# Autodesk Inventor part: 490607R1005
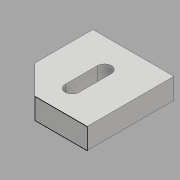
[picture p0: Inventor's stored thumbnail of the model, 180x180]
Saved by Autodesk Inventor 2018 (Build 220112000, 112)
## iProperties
Created: 2019-06
Part Number: 490607R1005
Material: 일반
Document SubType Name: Modeling
Designer: 6507_11
Density: 1 g/cm^3
Appearance: 기본값
Author: 6507_11
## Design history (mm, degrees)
sketch "스케치1"
  geometry: L1 (35, 37.5)-(-35, 37.5); L2 (-35, 37.5)-(-35, -12.5); L3 (-10, -37.5)-(35, -37.5); L4 (35, -37.5)-(35, 37.5); L5 (35, 37.5)-(-35, -37.5); L6 (-35, 37.5)-(35, -37.5); L7 (-10, -37.5)-(-35, -12.5); L8 (-35, 37.5)-(-35, -15.5); L9 (-35, -15.5)-(0, -15.5); L10 (6, 12.5)-(6, -15.5); L11 (-6, 12.5)-(-6, -15.5); A1 r 6 centre (0, -15.5) between (-6, -15.5) and (6, -15.5); A2 r 6 centre (0, 12.5) between (6, 12.5) and (-6, 12.5); 1 further point
  constraints: 22 end point, 4 point on circle, 3 parallel, 2 centre point, 2 midpoint, 2 perpendicular, 2 tangent, 1 coincident, 1 horizontal, 1 point on line, 1 vertical
  dimensions: "d0" = 70 distance of L3.end L5.end; "d1" = 75 distance of L5.end L1.end; "d3" = 45 deg angle of L3 L7; "d5" = 53 distance of L1.end L8.end; "d6" = 35 distance of L8.end L9.end; "d7" = 12 diameter of A1; "d9" = 12 diameter of A2
extrude "돌출1" new body sketch "스케치1" distance "d10" = 18; taper "d11" = 0 deg
sketch "스케치2"
  geometry: L1 (0, 0)-(45, 0) reference; L2 (45, 0)-(45, 18) reference; L3 (0, 18)-(45, 18) reference; L4 (0, 0)-(0, 18) reference; 1 further point
node "솔리드1"
